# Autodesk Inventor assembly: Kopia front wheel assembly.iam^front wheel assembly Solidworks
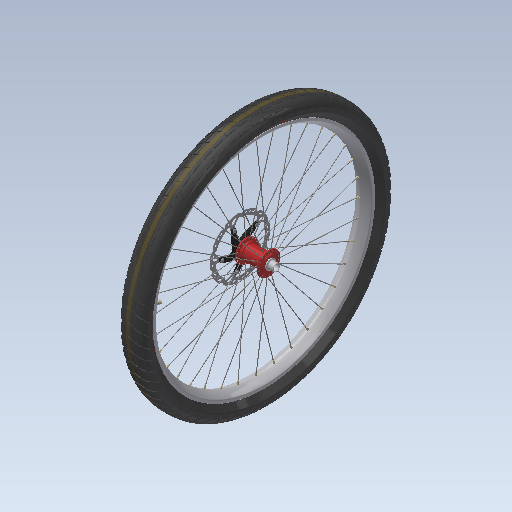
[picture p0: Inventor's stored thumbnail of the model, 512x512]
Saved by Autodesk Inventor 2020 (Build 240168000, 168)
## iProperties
Created: 2017-09
Part Number: Kopia front wheel assembly.iam^front wheel assembly Solidworks
Material: Ogólny
Document SubType Name: Assembly
Designer: Tomasz
Sending System: SolidWorks 2017
Last Author: Tomasz
Last Saved: 2017-11-20
Author: Tomasz
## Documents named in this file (12)
- C:\Users\bruno\Documents\1-Cours-2020-21\1STI2D-2020-21\IT\6. Antivol\Inventor-Antivol\INVENTOR 2018_Steel Hardtail B+\Kopia front wheel assembly.iam^front wheel assembly Solidworks.iam
- C:\Users\bruno\Documents\1-Cours-2020-21\1STI2D-2020-21\IT\6. Antivol\Inventor-Antivol\INVENTOR 2018_Steel Hardtail B+\Kopia Hope Pro2 BOOST 15mm.iam^Kopia front wheel assembly.iam_front wheel assembly Solidworks.iam
- C:\Users\bruno\Documents\1-Cours-2020-21\1STI2D-2020-21\IT\6. Antivol\Inventor-Antivol\INVENTOR 2018_Steel Hardtail B+\Kopia dt Swiss xm511.ipt^Kopia front wheel assembly.iam_front wheel assembly Solidworks.ipt
- C:\Users\bruno\Documents\1-Cours-2020-21\1STI2D-2020-21\IT\6. Antivol\Inventor-Antivol\INVENTOR 2018_Steel Hardtail B+\Kopia DT swiss 300 x 2mm.ipt^Kopia front wheel assembly.iam_front wheel assembly Solidworks.ipt
- C:\Users\bruno\Documents\1-Cours-2020-21\1STI2D-2020-21\IT\6. Antivol\Inventor-Antivol\INVENTOR 2018_Steel Hardtail B+\Kopia DT Swiss nipple.ipt^Kopia front wheel assembly.iam_front wheel assembly Solidworks.ipt
- C:\Users\bruno\Documents\1-Cours-2020-21\1STI2D-2020-21\IT\6. Antivol\Inventor-Antivol\INVENTOR 2018_Steel Hardtail B+\Kopia DT swiss 255 x 2mm - FR.ipt^Kopia front wheel assembly.iam_front wheel assembly Solidworks.ipt
- C:\Users\bruno\Documents\1-Cours-2020-21\1STI2D-2020-21\IT\6. Antivol\Inventor-Antivol\INVENTOR 2018_Steel Hardtail B+\Kopia Schwalbe Super Moto X 27,5 x 2,8.ipt^Kopia front wheel assembly.iam_front wheel assembly Solidworks.ipt
- C:\Users\bruno\Documents\1-Cours-2020-21\1STI2D-2020-21\IT\6. Antivol\Inventor-Antivol\INVENTOR 2018_Steel Hardtail B+\Kopia Rim tubeless tape with valve.ipt^Kopia front wheel assembly.iam_front wheel assembly Solidworks.ipt
- C:\Users\bruno\Documents\1-Cours-2020-21\1STI2D-2020-21\IT\6. Antivol\Inventor-Antivol\INVENTOR 2018_Steel Hardtail B+\Kopia Schrader_plug_valve.iam^Kopia front wheel assembly.iam_front wheel assembly Solidworks.iam
- C:\Users\bruno\Documents\1-Cours-2020-21\1STI2D-2020-21\IT\6. Antivol\Inventor-Antivol\INVENTOR 2018_Steel Hardtail B+\Kopia valve cap.ipt^Kopia front wheel assembly.iam_front wheel assembly Solidworks.ipt
- C:\Users\bruno\Documents\1-Cours-2020-21\1STI2D-2020-21\IT\6. Antivol\Inventor-Antivol\INVENTOR 2018_Steel Hardtail B+\Kopia Shimano XTR 160mm.iam^Kopia front wheel assembly.iam_front wheel assembly Solidworks.iam
- C:\Users\bruno\Documents\1-Cours-2020-21\1STI2D-2020-21\IT\6. Antivol\Inventor-Antivol\INVENTOR 2018_Steel Hardtail B+\Kopia Center Lock Nut.ipt^Kopia front wheel assembly.iam_front wheel assembly Solidworks.ipt
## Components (80 placed, 11 different names)
1. Kopia Hope Pro2 BOOST 15mm.iam^Kopia front wheel assembly.iam_front wheel assembly Solidworks:1 [sub-assembly]
2. Kopia dt Swiss xm511.ipt^Kopia front wheel assembly.iam_front wheel assembly Solidworks:1
3. Kopia DT swiss 300 x 2mm.ipt^Kopia front wheel assembly.iam_front wheel assembly Solidworks:1
4. Kopia DT swiss 300 x 2mm.ipt^Kopia front wheel assembly.iam_front wheel assembly Solidworks:2
5. Kopia DT swiss 300 x 2mm.ipt^Kopia front wheel assembly.iam_front wheel assembly Solidworks:3
6. Kopia DT swiss 300 x 2mm.ipt^Kopia front wheel assembly.iam_front wheel assembly Solidworks:4
7. Kopia DT swiss 300 x 2mm.ipt^Kopia front wheel assembly.iam_front wheel assembly Solidworks:5
8. Kopia DT swiss 300 x 2mm.ipt^Kopia front wheel assembly.iam_front wheel assembly Solidworks:6
9. Kopia DT swiss 300 x 2mm.ipt^Kopia front wheel assembly.iam_front wheel assembly Solidworks:7
10. Kopia DT swiss 300 x 2mm.ipt^Kopia front wheel assembly.iam_front wheel assembly Solidworks:8
11. Kopia DT swiss 300 x 2mm.ipt^Kopia front wheel assembly.iam_front wheel assembly Solidworks:9
12. Kopia DT swiss 300 x 2mm.ipt^Kopia front wheel assembly.iam_front wheel assembly Solidworks:10
13. Kopia DT swiss 300 x 2mm.ipt^Kopia front wheel assembly.iam_front wheel assembly Solidworks:11
14. Kopia DT swiss 300 x 2mm.ipt^Kopia front wheel assembly.iam_front wheel assembly Solidworks:12
15. Kopia DT swiss 300 x 2mm.ipt^Kopia front wheel assembly.iam_front wheel assembly Solidworks:13
16. Kopia DT swiss 300 x 2mm.ipt^Kopia front wheel assembly.iam_front wheel assembly Solidworks:14
17. Kopia DT swiss 300 x 2mm.ipt^Kopia front wheel assembly.iam_front wheel assembly Solidworks:15
18. Kopia DT swiss 300 x 2mm.ipt^Kopia front wheel assembly.iam_front wheel assembly Solidworks:16
19. Kopia DT swiss 300 x 2mm.ipt^Kopia front wheel assembly.iam_front wheel assembly Solidworks:17
20. Kopia DT swiss 300 x 2mm.ipt^Kopia front wheel assembly.iam_front wheel assembly Solidworks:18
21. Kopia DT Swiss nipple.ipt^Kopia front wheel assembly.iam_front wheel assembly Solidworks:1
22. Kopia DT Swiss nipple.ipt^Kopia front wheel assembly.iam_front wheel assembly Solidworks:2
23. Kopia DT Swiss nipple.ipt^Kopia front wheel assembly.iam_front wheel assembly Solidworks:3
24. Kopia DT Swiss nipple.ipt^Kopia front wheel assembly.iam_front wheel assembly Solidworks:4
25. Kopia DT Swiss nipple.ipt^Kopia front wheel assembly.iam_front wheel assembly Solidworks:5
26. Kopia DT Swiss nipple.ipt^Kopia front wheel assembly.iam_front wheel assembly Solidworks:6
27. Kopia DT Swiss nipple.ipt^Kopia front wheel assembly.iam_front wheel assembly Solidworks:7
28. Kopia DT Swiss nipple.ipt^Kopia front wheel assembly.iam_front wheel assembly Solidworks:8
29. Kopia DT Swiss nipple.ipt^Kopia front wheel assembly.iam_front wheel assembly Solidworks:9
30. Kopia DT Swiss nipple.ipt^Kopia front wheel assembly.iam_front wheel assembly Solidworks:10
31. Kopia DT Swiss nipple.ipt^Kopia front wheel assembly.iam_front wheel assembly Solidworks:11
32. Kopia DT Swiss nipple.ipt^Kopia front wheel assembly.iam_front wheel assembly Solidworks:12
33. Kopia DT Swiss nipple.ipt^Kopia front wheel assembly.iam_front wheel assembly Solidworks:13
34. Kopia DT Swiss nipple.ipt^Kopia front wheel assembly.iam_front wheel assembly Solidworks:14
35. Kopia DT Swiss nipple.ipt^Kopia front wheel assembly.iam_front wheel assembly Solidworks:15
36. Kopia DT Swiss nipple.ipt^Kopia front wheel assembly.iam_front wheel assembly Solidworks:16
37. Kopia DT Swiss nipple.ipt^Kopia front wheel assembly.iam_front wheel assembly Solidworks:17
38. Kopia DT Swiss nipple.ipt^Kopia front wheel assembly.iam_front wheel assembly Solidworks:18
39. Kopia DT Swiss nipple.ipt^Kopia front wheel assembly.iam_front wheel assembly Solidworks:19
40. Kopia DT Swiss nipple.ipt^Kopia front wheel assembly.iam_front wheel assembly Solidworks:20
41. Kopia DT Swiss nipple.ipt^Kopia front wheel assembly.iam_front wheel assembly Solidworks:21
42. Kopia DT Swiss nipple.ipt^Kopia front wheel assembly.iam_front wheel assembly Solidworks:22
43. Kopia DT Swiss nipple.ipt^Kopia front wheel assembly.iam_front wheel assembly Solidworks:23
44. Kopia DT Swiss nipple.ipt^Kopia front wheel assembly.iam_front wheel assembly Solidworks:24
45. Kopia DT Swiss nipple.ipt^Kopia front wheel assembly.iam_front wheel assembly Solidworks:25
46. Kopia DT Swiss nipple.ipt^Kopia front wheel assembly.iam_front wheel assembly Solidworks:26
47. Kopia DT Swiss nipple.ipt^Kopia front wheel assembly.iam_front wheel assembly Solidworks:27
48. Kopia DT Swiss nipple.ipt^Kopia front wheel assembly.iam_front wheel assembly Solidworks:28
49. Kopia DT Swiss nipple.ipt^Kopia front wheel assembly.iam_front wheel assembly Solidworks:29
50. Kopia DT Swiss nipple.ipt^Kopia front wheel assembly.iam_front wheel assembly Solidworks:30
51. Kopia DT Swiss nipple.ipt^Kopia front wheel assembly.iam_front wheel assembly Solidworks:31
52. Kopia DT Swiss nipple.ipt^Kopia front wheel assembly.iam_front wheel assembly Solidworks:32
53. Kopia DT Swiss nipple.ipt^Kopia front wheel assembly.iam_front wheel assembly Solidworks:33
54. Kopia DT Swiss nipple.ipt^Kopia front wheel assembly.iam_front wheel assembly Solidworks:34
55. Kopia DT Swiss nipple.ipt^Kopia front wheel assembly.iam_front wheel assembly Solidworks:35
56. Kopia DT Swiss nipple.ipt^Kopia front wheel assembly.iam_front wheel assembly Solidworks:36
57. Kopia DT swiss 255 x 2mm - FR.ipt^Kopia front wheel assembly.iam_front wheel assembly Solidworks:1
58. Kopia DT swiss 255 x 2mm - FR.ipt^Kopia front wheel assembly.iam_front wheel assembly Solidworks:2
59. Kopia DT swiss 255 x 2mm - FR.ipt^Kopia front wheel assembly.iam_front wheel assembly Solidworks:3
60. Kopia DT swiss 255 x 2mm - FR.ipt^Kopia front wheel assembly.iam_front wheel assembly Solidworks:4
61. Kopia DT swiss 255 x 2mm - FR.ipt^Kopia front wheel assembly.iam_front wheel assembly Solidworks:5
62. Kopia DT swiss 255 x 2mm - FR.ipt^Kopia front wheel assembly.iam_front wheel assembly Solidworks:6
63. Kopia DT swiss 255 x 2mm - FR.ipt^Kopia front wheel assembly.iam_front wheel assembly Solidworks:7
64. Kopia DT swiss 255 x 2mm - FR.ipt^Kopia front wheel assembly.iam_front wheel assembly Solidworks:8
65. Kopia DT swiss 255 x 2mm - FR.ipt^Kopia front wheel assembly.iam_front wheel assembly Solidworks:9
66. Kopia DT swiss 255 x 2mm - FR.ipt^Kopia front wheel assembly.iam_front wheel assembly Solidworks:10
67. Kopia DT swiss 255 x 2mm - FR.ipt^Kopia front wheel assembly.iam_front wheel assembly Solidworks:11
68. Kopia DT swiss 255 x 2mm - FR.ipt^Kopia front wheel assembly.iam_front wheel assembly Solidworks:12
69. Kopia DT swiss 255 x 2mm - FR.ipt^Kopia front wheel assembly.iam_front wheel assembly Solidworks:13
70. Kopia DT swiss 255 x 2mm - FR.ipt^Kopia front wheel assembly.iam_front wheel assembly Solidworks:14
71. Kopia DT swiss 255 x 2mm - FR.ipt^Kopia front wheel assembly.iam_front wheel assembly Solidworks:15
72. Kopia DT swiss 255 x 2mm - FR.ipt^Kopia front wheel assembly.iam_front wheel assembly Solidworks:16
73. Kopia DT swiss 255 x 2mm - FR.ipt^Kopia front wheel assembly.iam_front wheel assembly Solidworks:17
74. Kopia DT swiss 255 x 2mm - FR.ipt^Kopia front wheel assembly.iam_front wheel assembly Solidworks:18
75. Kopia Schwalbe Super Moto X 27,5 x 2,8.ipt^Kopia front wheel assembly.iam_front wheel assembly Solidworks:1
76. Kopia Rim tubeless tape with valve.ipt^Kopia front wheel assembly.iam_front wheel assembly Solidworks:1
77. Kopia Schrader_plug_valve.iam^Kopia front wheel assembly.iam_front wheel assembly Solidworks:1 [sub-assembly]
78. Kopia valve cap.ipt^Kopia front wheel assembly.iam_front wheel assembly Solidworks:1
79. Kopia Shimano XTR 160mm.iam^Kopia front wheel assembly.iam_front wheel assembly Solidworks:1 [sub-assembly]
80. Kopia Center Lock Nut.ipt^Kopia front wheel assembly.iam_front wheel assembly Solidworks:1
